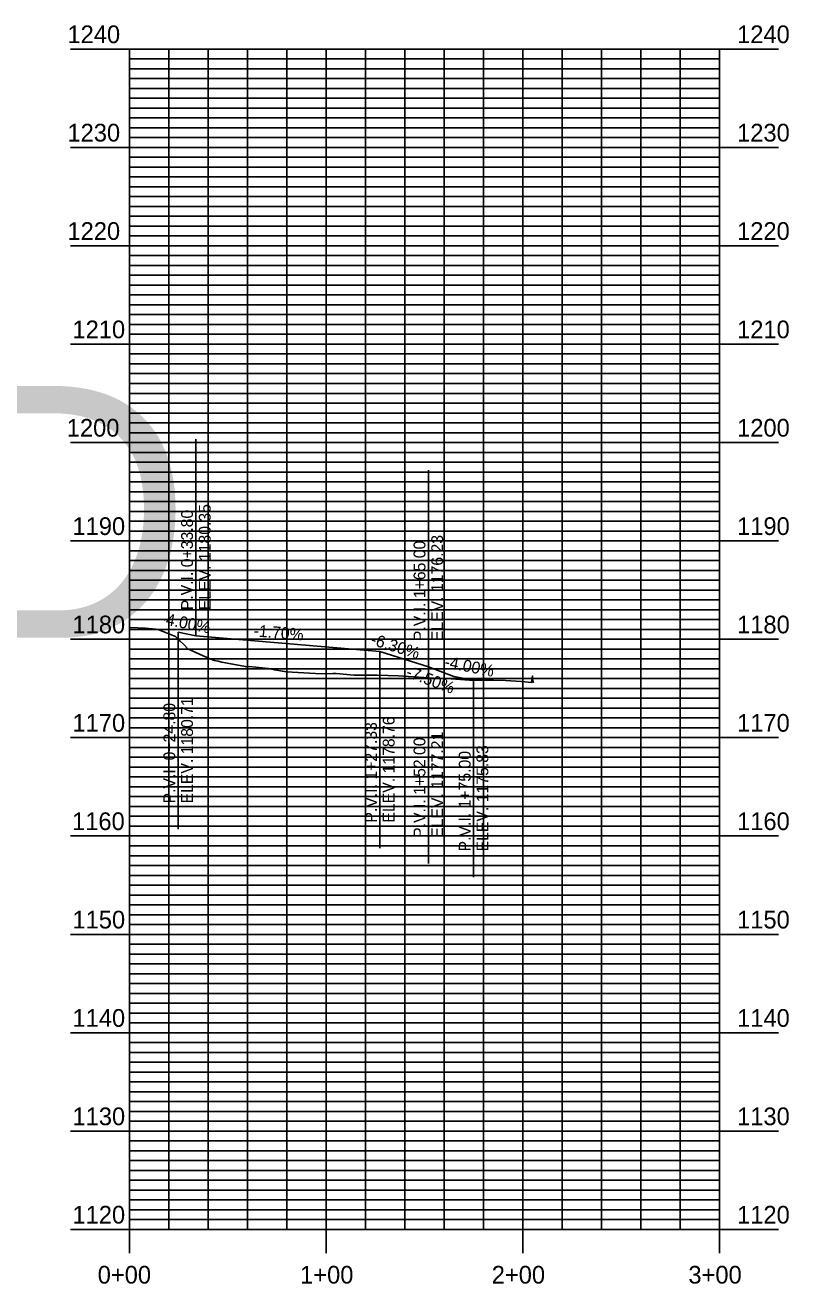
# Model space of a CAD drawing. Extents: x 604436 to 613248, y 742914 to 744515.
# Drawn here: x 605260 to 605648, y 742914 to 743553 of the extents above; entities that cross this region are included whole.
import ezdxf

# ---------------------------------------------------------------- set-up
doc = ezdxf.new("R2010")
doc.units = 0
for name, color, linetype in [('51', 7, 'Continuous'), ('Grid', 7, 'Continuous'), ('Grid_Labels', 7, 'Continuous'), ('Grid_Major', 7, 'Continuous'), ('Grid_Minor', 7, 'Continuous'), ('PRF_RD_Ex_PGL', 7, 'Continuous'), ('PRF_Scratch_1', 7, 'Continuous'), ('Profile', 7, 'Continuous'), ('Profile Annotation', 7, 'Continuous'), ('Profile Annotation Line', 7, 'Continuous')]:
    doc.layers.add(name, color=color, linetype=linetype)

msp = doc.modelspace()

# ---------------------------------------------------------------- linework, layer by layer
at = {"layer": 'Grid'}
for p, q in [((605283.12, 743541.35), (605313.12, 743541.35)), ((605283.12, 743541.35), (605313.12, 743541.35)), ((605313.12, 742941.35), (605313.12, 743541.35)), ((605613.12, 742941.35), (605613.12, 743541.35)), ((605643.12, 743541.35), (605613.12, 743541.35)), ((605643.12, 743541.35), (605613.12, 743541.35)), ((605313.12, 743536.35), (605316.12, 743536.35)), ((605313.12, 743531.35), (605316.12, 743531.35)), ((605313.12, 743526.35), (605316.12, 743526.35)), ((605313.12, 743521.35), (605316.12, 743521.35)), ((605313.12, 743516.35), (605316.12, 743516.35)), ((605313.12, 743511.35), (605316.12, 743511.35)), ((605313.12, 743506.35), (605316.12, 743506.35)), ((605313.12, 743501.35), (605316.12, 743501.35)), ((605313.12, 743496.35), (605316.12, 743496.35)), ((605283.12, 743491.35), (605313.12, 743491.35)), ((605643.12, 743491.35), (605613.12, 743491.35)), ((605313.12, 743486.35), (605316.12, 743486.35)), ((605313.12, 743481.35), (605316.12, 743481.35)), ((605313.12, 743476.35), (605316.12, 743476.35)), ((605313.12, 743471.35), (605316.12, 743471.35)), ((605313.12, 743466.35), (605316.12, 743466.35)), ((605313.12, 743461.35), (605316.12, 743461.35)), ((605313.12, 743456.35), (605316.12, 743456.35)), ((605313.12, 743451.35), (605316.12, 743451.35)), ((605313.12, 743446.35), (605316.12, 743446.35)), ((605283.12, 743441.35), (605313.12, 743441.35)), ((605313.12, 743436.35), (605316.12, 743436.35)), ((605643.12, 743441.35), (605613.12, 743441.35)), ((605313.12, 743431.35), (605316.12, 743431.35)), ((605313.12, 743426.35), (605316.12, 743426.35)), ((605313.12, 743421.35), (605316.12, 743421.35)), ((605313.12, 743416.35), (605316.12, 743416.35)), ((605313.12, 743411.35), (605316.12, 743411.35)), ((605313.12, 743406.35), (605316.12, 743406.35)), ((605313.12, 743401.35), (605316.12, 743401.35)), ((605283.12, 743391.35), (605313.12, 743391.35)), ((605313.12, 743396.35), (605316.12, 743396.35)), ((605643.12, 743391.35), (605613.12, 743391.35)), ((605313.12, 743386.35), (605316.12, 743386.35)), ((605313.12, 743381.35), (605316.12, 743381.35)), ((605313.12, 743376.35), (605316.12, 743376.35)), ((605313.12, 743371.35), (605316.12, 743371.35)), ((605313.12, 743366.35), (605316.12, 743366.35)), ((605313.12, 743361.35), (605316.12, 743361.35)), ((605313.12, 743356.35), (605316.12, 743356.35)), ((605313.12, 743351.35), (605316.12, 743351.35)), ((605313.12, 743346.35), (605316.12, 743346.35)), ((605283.12, 743341.35), (605313.12, 743341.35)), ((605643.12, 743341.35), (605613.12, 743341.35)), ((605313.12, 743336.35), (605316.12, 743336.35)), ((605313.12, 743331.35), (605316.12, 743331.35)), ((605313.12, 743326.35), (605316.12, 743326.35)), ((605313.12, 743321.35), (605316.12, 743321.35)), ((605313.12, 743316.35), (605316.12, 743316.35)), ((605313.12, 743311.35), (605316.12, 743311.35)), ((605313.12, 743306.35), (605316.12, 743306.35)), ((605313.12, 743301.35), (605316.12, 743301.35)), ((605313.12, 743296.35), (605316.12, 743296.35)), ((605283.12, 743291.35), (605313.12, 743291.35)), ((605643.12, 743291.35), (605613.12, 743291.35)), ((605313.12, 743286.35), (605316.12, 743286.35)), ((605313.12, 743281.35), (605316.12, 743281.35)), ((605313.12, 743276.35), (605316.12, 743276.35)), ((605313.12, 743271.35), (605316.12, 743271.35)), ((605313.12, 743266.35), (605316.12, 743266.35)), ((605313.12, 743261.35), (605316.12, 743261.35)), ((605313.12, 743256.35), (605316.12, 743256.35)), ((605313.12, 743251.35), (605316.12, 743251.35)), ((605313.12, 743246.35), (605316.12, 743246.35)), ((605283.12, 743241.35), (605313.12, 743241.35)), ((605643.12, 743241.35), (605613.12, 743241.35)), ((605313.12, 743236.35), (605316.12, 743236.35)), ((605313.12, 743231.35), (605316.12, 743231.35)), ((605313.12, 743226.35), (605316.12, 743226.35)), ((605313.12, 743221.35), (605316.12, 743221.35)), ((605313.12, 743216.35), (605316.12, 743216.35)), ((605313.12, 743211.35), (605316.12, 743211.35)), ((605313.12, 743206.35), (605316.12, 743206.35)), ((605313.12, 743201.35), (605316.12, 743201.35)), ((605313.12, 743196.35), (605316.12, 743196.35)), ((605283.12, 743191.35), (605313.12, 743191.35)), ((605313.12, 743186.35), (605316.12, 743186.35)), ((605643.12, 743191.35), (605613.12, 743191.35)), ((605313.12, 743181.35), (605316.12, 743181.35)), ((605313.12, 743176.35), (605316.12, 743176.35)), ((605313.12, 743171.35), (605316.12, 743171.35)), ((605313.12, 743166.35), (605316.12, 743166.35)), ((605313.12, 743161.35), (605316.12, 743161.35)), ((605313.12, 743156.35), (605316.12, 743156.35)), ((605313.12, 743151.35), (605316.12, 743151.35)), ((605283.12, 743141.35), (605313.12, 743141.35)), ((605313.12, 743146.35), (605316.12, 743146.35)), ((605643.12, 743141.35), (605613.12, 743141.35)), ((605313.12, 743136.35), (605316.12, 743136.35)), ((605313.12, 743131.35), (605316.12, 743131.35)), ((605313.12, 743126.35), (605316.12, 743126.35)), ((605313.12, 743121.35), (605316.12, 743121.35)), ((605313.12, 743116.35), (605316.12, 743116.35)), ((605313.12, 743111.35), (605316.12, 743111.35)), ((605313.12, 743106.35), (605316.12, 743106.35)), ((605313.12, 743101.35), (605316.12, 743101.35)), ((605313.12, 743096.35), (605316.12, 743096.35)), ((605283.12, 743091.35), (605313.12, 743091.35)), ((605643.12, 743091.35), (605613.12, 743091.35)), ((605313.12, 743086.35), (605316.12, 743086.35)), ((605313.12, 743081.35), (605316.12, 743081.35)), ((605313.12, 743076.35), (605316.12, 743076.35)), ((605313.12, 743071.35), (605316.12, 743071.35)), ((605313.12, 743066.35), (605316.12, 743066.35)), ((605313.12, 743061.35), (605316.12, 743061.35)), ((605313.12, 743056.35), (605316.12, 743056.35)), ((605313.12, 743051.35), (605316.12, 743051.35)), ((605313.12, 743046.35), (605316.12, 743046.35)), ((605283.12, 743041.35), (605313.12, 743041.35)), ((605643.12, 743041.35), (605613.12, 743041.35)), ((605313.12, 743036.35), (605316.12, 743036.35)), ((605313.12, 743031.35), (605316.12, 743031.35)), ((605313.12, 743026.35), (605316.12, 743026.35)), ((605313.12, 743021.35), (605316.12, 743021.35)), ((605313.12, 743016.35), (605316.12, 743016.35)), ((605313.12, 743011.35), (605316.12, 743011.35)), ((605313.12, 743006.35), (605316.12, 743006.35)), ((605313.12, 743001.35), (605316.12, 743001.35)), ((605313.12, 742996.35), (605316.12, 742996.35)), ((605283.12, 742991.35), (605313.12, 742991.35)), ((605643.12, 742991.35), (605613.12, 742991.35)), ((605313.12, 742986.35), (605316.12, 742986.35)), ((605313.12, 742981.35), (605316.12, 742981.35)), ((605313.12, 742976.35), (605316.12, 742976.35)), ((605313.12, 742971.35), (605316.12, 742971.35)), ((605313.12, 742966.35), (605316.12, 742966.35)), ((605313.12, 742961.35), (605316.12, 742961.35)), ((605313.12, 742956.35), (605316.12, 742956.35)), ((605313.12, 742951.35), (605316.12, 742951.35)), ((605313.12, 742946.35), (605316.12, 742946.35)), ((605283.12, 742941.35), (605313.12, 742941.35)), ((605313.12, 742941.35), (605613.12, 742941.35)), ((605313.12, 742929.35), (605313.12, 742941.35)), ((605413.12, 742929.35), (605413.12, 742941.35)), ((605513.12, 742929.35), (605513.12, 742941.35)), ((605643.12, 742941.35), (605613.12, 742941.35)), ((605613.12, 742929.35), (605613.12, 742941.35))]:
    msp.add_line(p, q, dxfattribs=at)
at = {"layer": 'Grid_Major'}
for p, q in [((605313.12, 743541.35), (605613.12, 743541.35)), ((605313.12, 743541.35), (605613.12, 743541.35)), ((605413.12, 742941.35), (605413.12, 743541.35)), ((605513.12, 742941.35), (605513.12, 743541.35)), ((605313.12, 743491.35), (605613.12, 743491.35)), ((605313.12, 743441.35), (605613.12, 743441.35)), ((605313.12, 743391.35), (605613.12, 743391.35)), ((605313.12, 743341.35), (605613.12, 743341.35)), ((605313.12, 743291.35), (605613.12, 743291.35)), ((605313.12, 743241.35), (605613.12, 743241.35)), ((605313.12, 743191.35), (605613.12, 743191.35)), ((605313.12, 743141.35), (605613.12, 743141.35)), ((605313.12, 743091.35), (605613.12, 743091.35)), ((605313.12, 743041.35), (605613.12, 743041.35)), ((605313.12, 742991.35), (605613.12, 742991.35))]:
    msp.add_line(p, q, dxfattribs=at)
at = {"layer": 'Grid_Minor'}
for p, q in [((605333.12, 742941.35), (605333.12, 743541.35)), ((605353.12, 742941.35), (605353.12, 743541.35)), ((605373.12, 742941.35), (605373.12, 743541.35)), ((605393.12, 742941.35), (605393.12, 743541.35)), ((605433.12, 742941.35), (605433.12, 743541.35)), ((605453.12, 742941.35), (605453.12, 743541.35)), ((605473.12, 742941.35), (605473.12, 743541.35)), ((605493.12, 742941.35), (605493.12, 743541.35)), ((605533.12, 742941.35), (605533.12, 743541.35)), ((605553.12, 742941.35), (605553.12, 743541.35)), ((605573.12, 742941.35), (605573.12, 743541.35)), ((605593.12, 742941.35), (605593.12, 743541.35)), ((605313.12, 743536.35), (605613.12, 743536.35)), ((605313.12, 743531.35), (605613.12, 743531.35)), ((605313.12, 743526.35), (605613.12, 743526.35)), ((605313.12, 743521.35), (605613.12, 743521.35)), ((605313.12, 743516.35), (605613.12, 743516.35)), ((605313.12, 743511.35), (605613.12, 743511.35)), ((605313.12, 743506.35), (605613.12, 743506.35)), ((605313.12, 743501.35), (605613.12, 743501.35)), ((605313.12, 743496.35), (605613.12, 743496.35)), ((605313.12, 743486.35), (605613.12, 743486.35)), ((605313.12, 743481.35), (605613.12, 743481.35)), ((605313.12, 743476.35), (605613.12, 743476.35)), ((605313.12, 743471.35), (605613.12, 743471.35)), ((605313.12, 743466.35), (605613.12, 743466.35)), ((605313.12, 743461.35), (605613.12, 743461.35)), ((605313.12, 743456.35), (605613.12, 743456.35)), ((605313.12, 743451.35), (605613.12, 743451.35)), ((605313.12, 743446.35), (605613.12, 743446.35)), ((605313.12, 743436.35), (605613.12, 743436.35)), ((605313.12, 743431.35), (605613.12, 743431.35)), ((605313.12, 743426.35), (605613.12, 743426.35)), ((605313.12, 743421.35), (605613.12, 743421.35)), ((605313.12, 743416.35), (605613.12, 743416.35)), ((605313.12, 743411.35), (605613.12, 743411.35)), ((605313.12, 743406.35), (605613.12, 743406.35)), ((605313.12, 743401.35), (605613.12, 743401.35)), ((605313.12, 743396.35), (605613.12, 743396.35)), ((605313.12, 743386.35), (605613.12, 743386.35)), ((605313.12, 743381.35), (605613.12, 743381.35)), ((605313.12, 743376.35), (605613.12, 743376.35)), ((605313.12, 743371.35), (605613.12, 743371.35)), ((605313.12, 743366.35), (605613.12, 743366.35)), ((605313.12, 743361.35), (605613.12, 743361.35)), ((605313.12, 743356.35), (605613.12, 743356.35)), ((605313.12, 743351.35), (605613.12, 743351.35)), ((605313.12, 743346.35), (605613.12, 743346.35)), ((605313.12, 743336.35), (605613.12, 743336.35)), ((605313.12, 743331.35), (605613.12, 743331.35)), ((605313.12, 743326.35), (605613.12, 743326.35)), ((605313.12, 743321.35), (605613.12, 743321.35)), ((605313.12, 743316.35), (605613.12, 743316.35)), ((605313.12, 743311.35), (605613.12, 743311.35)), ((605313.12, 743306.35), (605613.12, 743306.35)), ((605313.12, 743301.35), (605613.12, 743301.35)), ((605313.12, 743296.35), (605613.12, 743296.35)), ((605313.12, 743286.35), (605613.12, 743286.35)), ((605313.12, 743281.35), (605613.12, 743281.35)), ((605313.12, 743276.35), (605613.12, 743276.35)), ((605313.12, 743271.35), (605613.12, 743271.35)), ((605313.12, 743266.35), (605613.12, 743266.35)), ((605313.12, 743261.35), (605613.12, 743261.35)), ((605313.12, 743256.35), (605613.12, 743256.35)), ((605313.12, 743251.35), (605613.12, 743251.35)), ((605313.12, 743246.35), (605613.12, 743246.35)), ((605313.12, 743236.35), (605613.12, 743236.35)), ((605313.12, 743231.35), (605613.12, 743231.35)), ((605313.12, 743226.35), (605613.12, 743226.35)), ((605313.12, 743221.35), (605613.12, 743221.35)), ((605313.12, 743216.35), (605613.12, 743216.35)), ((605313.12, 743211.35), (605613.12, 743211.35)), ((605313.12, 743206.35), (605613.12, 743206.35)), ((605313.12, 743201.35), (605613.12, 743201.35)), ((605313.12, 743196.35), (605613.12, 743196.35)), ((605313.12, 743186.35), (605613.12, 743186.35)), ((605313.12, 743181.35), (605613.12, 743181.35)), ((605313.12, 743176.35), (605613.12, 743176.35)), ((605313.12, 743171.35), (605613.12, 743171.35)), ((605313.12, 743166.35), (605613.12, 743166.35)), ((605313.12, 743161.35), (605613.12, 743161.35)), ((605313.12, 743156.35), (605613.12, 743156.35)), ((605313.12, 743151.35), (605613.12, 743151.35)), ((605313.12, 743146.35), (605613.12, 743146.35)), ((605313.12, 743136.35), (605613.12, 743136.35)), ((605313.12, 743131.35), (605613.12, 743131.35)), ((605313.12, 743126.35), (605613.12, 743126.35)), ((605313.12, 743121.35), (605613.12, 743121.35)), ((605313.12, 743116.35), (605613.12, 743116.35)), ((605313.12, 743111.35), (605613.12, 743111.35)), ((605313.12, 743106.35), (605613.12, 743106.35)), ((605313.12, 743101.35), (605613.12, 743101.35)), ((605313.12, 743096.35), (605613.12, 743096.35)), ((605313.12, 743086.35), (605613.12, 743086.35)), ((605313.12, 743081.35), (605613.12, 743081.35)), ((605313.12, 743076.35), (605613.12, 743076.35)), ((605313.12, 743071.35), (605613.12, 743071.35)), ((605313.12, 743066.35), (605613.12, 743066.35)), ((605313.12, 743061.35), (605613.12, 743061.35)), ((605313.12, 743056.35), (605613.12, 743056.35)), ((605313.12, 743051.35), (605613.12, 743051.35)), ((605313.12, 743046.35), (605613.12, 743046.35)), ((605313.12, 743036.35), (605613.12, 743036.35)), ((605313.12, 743031.35), (605613.12, 743031.35)), ((605313.12, 743026.35), (605613.12, 743026.35)), ((605313.12, 743021.35), (605613.12, 743021.35)), ((605313.12, 743016.35), (605613.12, 743016.35)), ((605313.12, 743011.35), (605613.12, 743011.35)), ((605313.12, 743006.35), (605613.12, 743006.35)), ((605313.12, 743001.35), (605613.12, 743001.35)), ((605313.12, 742996.35), (605613.12, 742996.35)), ((605313.12, 742986.35), (605613.12, 742986.35)), ((605313.12, 742981.35), (605613.12, 742981.35)), ((605313.12, 742976.35), (605613.12, 742976.35)), ((605313.12, 742971.35), (605613.12, 742971.35)), ((605313.12, 742966.35), (605613.12, 742966.35)), ((605313.12, 742961.35), (605613.12, 742961.35)), ((605313.12, 742956.35), (605613.12, 742956.35)), ((605313.12, 742951.35), (605613.12, 742951.35)), ((605313.12, 742946.35), (605613.12, 742946.35))]:
    msp.add_line(p, q, dxfattribs=at)
at = {"layer": 'PRF_RD_Ex_PGL'}
msp.add_lwpolyline([(605313.12, 743247.31), (605313.44, 743247.31), (605321.3, 743246.95), (605326.61, 743246.55), (605328.07, 743246.07), (605336.61, 743242.67), (605338.64, 743240.59), (605339, 743240.31), (605340.54, 743238.81), (605342.98, 743236.39), (605343.12, 743236.32), (605344.36, 743235.75), (605345.02, 743235.45), (605346.91, 743234.58), (605348.8, 743233.74), (605350.69, 743232.9), (605352.58, 743232.07), (605354.47, 743231.26), (605355.92, 743230.65), (605356.36, 743230.56), (605358.25, 743230.16), (605360.14, 743229.78), (605362.03, 743229.41), (605372.2, 743227.42), (605372.39, 743227.38), (605372.43, 743227.39), (605374.22, 743227.53), (605383.79, 743226.51), (605386.86, 743225.76), (605390.88, 743225.06), (605392.94, 743224.87), (605410.61, 743223.75), (605416.52, 743223.9), (605417.94, 743223.93), (605418.29, 743223.91), (605420.07, 743223.76), (605421.85, 743223.62), (605423.62, 743223.47), (605425.4, 743223.32), (605427.17, 743223.17), (605428.2, 743223.08), (605428.95, 743223.09), (605430.73, 743223.09), (605432.5, 743223.09), (605439.17, 743223.09), (605449.92, 743222.76), (605457.64, 743222.28), (605468.15, 743221.65), (605476.81, 743221.15), (605486.03, 743220.49), (605498.32, 743220.57), (605504.37, 743220.35), (605512.46, 743219.81), (605517.63, 743219.39), (605518, 743222.68), (605518.15, 743220.86), (605518.39, 743219.77), (605518.52, 743219.23)], dxfattribs=at)
at = {"layer": 'Profile'}
for p, q in [((605337.92, 743244.89), (605346.92, 743243.09)), ((605346.92, 743243.09), (605440.45, 743235.15)), ((605440.45, 743235.15), (605465.12, 743227.38)), ((605465.12, 743227.38), (605478.12, 743222.5)), ((605478.12, 743222.5), (605488.12, 743220.5))]:
    msp.add_line(p, q, dxfattribs=at)
at = {"layer": 'Profile Annotation Line'}
for p, q in [((605346.92, 743343.09), (605346.92, 743243.09)), ((605465.12, 743327.38), (605465.12, 743227.38)), ((605337.92, 743244.89), (605337.92, 743144.89)), ((605440.45, 743235.15), (605440.45, 743135.15)), ((605465.12, 743227.38), (605465.12, 743127.38)), ((605488.12, 743220.5), (605488.12, 743120.5))]:
    msp.add_line(p, q, dxfattribs=at)

# ---------------------------------------------------------------- texts
at = {"layer": '51'}
msp.add_text('-', height=0.0001, dxfattribs=at).set_placement((605313.12, 742941.35))
at = {"layer": 'Grid_Labels'}
for s, p in [('1240', (605281.62, 743544.35)), ('1240', (605281.62, 743544.35)), ('1240', (605622.12, 743544.35)), ('1240', (605622.12, 743544.35)), ('1230', (605281.62, 743494.35)), ('1230', (605622.12, 743494.35)), ('1220', (605281.62, 743444.35)), ('1220', (605622.12, 743444.35)), ('1210', (605284.17, 743394.35)), ('1210', (605622.12, 743394.35)), ('1200', (605281.26, 743344.35)), ('1200', (605622.12, 743344.35)), ('1190', (605284.17, 743294.35)), ('1190', (605622.12, 743294.35)), ('1180', (605284.17, 743244.35)), ('1180', (605622.12, 743244.35)), ('1170', (605284.17, 743194.35)), ('1170', (605622.12, 743194.35)), ('1160', (605283.96, 743144.35)), ('1160', (605622.12, 743144.35)), ('1150', (605284.17, 743094.35)), ('1150', (605622.12, 743094.35)), ('1140', (605284.17, 743044.35)), ('1140', (605622.12, 743044.35)), ('1130', (605284.17, 742994.35)), ('1130', (605622.12, 742994.35)), ('1120', (605284.17, 742944.35)), ('1120', (605622.12, 742944.35)), ('0+00', (605297, 742913.85)), ('1+00', (605399.91, 742913.85)), ('2+00', (605497.36, 742913.85)), ('3+00', (605597.36, 742913.85))]:
    msp.add_text(s, height=9, dxfattribs=at).set_placement(p)
at = {"layer": 'PRF_Scratch_1'}
msp.add_text('HODGE RD', height=128, dxfattribs=at).set_placement((604422.33, 743242.14))
at = {"layer": 'Profile Annotation'}
for s, rotation, p in [('ELEV. 1180.35', 90, (605354.42, 743256.09)), ('P.V.I. 0+33.80', 90, (605345.42, 743256.09)), ('P.V.I. 1+65.00', 90, (605463.62, 743240.38)), ('ELEV. 1176.23', 90, (605472.62, 743240.38)), ('-4.00%', 348.69007, (605328.7, 743249.26)), ('-1.70%', 355.14765, (605376.11, 743242.84)), ('-6.30%', 342.51557, (605435.35, 743238.81)), ('-4.00%', 348.69007, (605472.98, 743227.17)), ('-7.50%', 339.44395, (605453.3, 743222.42)), ('ELEV. 1180.71', 90, (605345.42, 743157.89)), ('P.V.I. 0+24.80', 90, (605336.42, 743157.89)), ('P.V.I. 1+27.33', 90, (605438.95, 743148.15)), ('ELEV. 1178.76', 90, (605447.95, 743148.15)), ('ELEV. 1177.21', 90, (605472.62, 743140.38)), ('P.V.I. 1+52.00', 90, (605463.62, 743140.38)), ('ELEV. 1175.83', 90, (605495.62, 743133.5)), ('P.V.I. 1+75.00', 90, (605486.62, 743133.5))]:
    msp.add_text(s, height=6, rotation=rotation, dxfattribs=at).set_placement(p)

doc.saveas('drawing.dxf')
